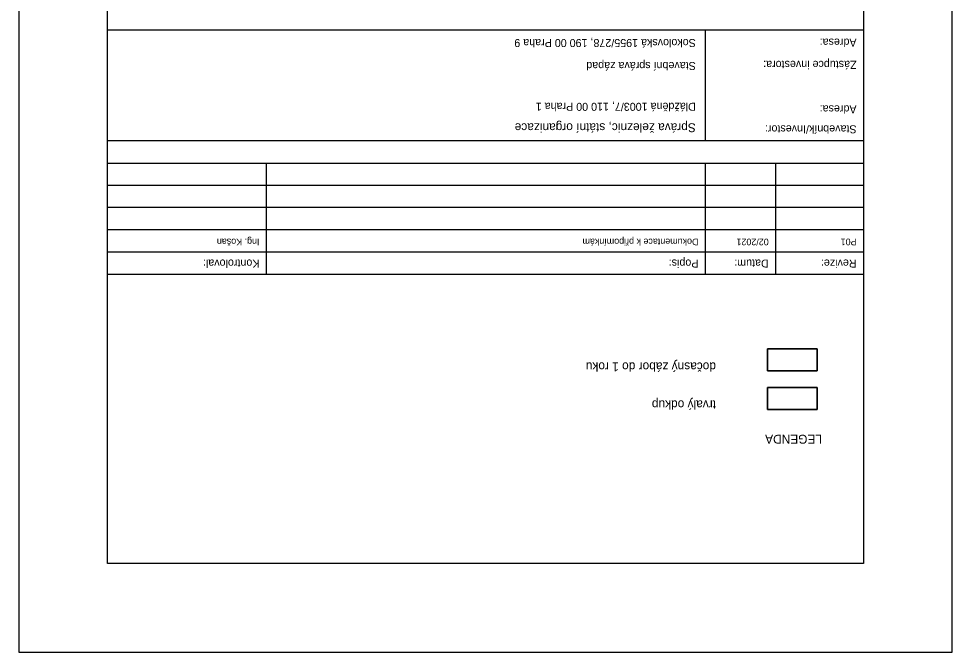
# Model space of a CAD drawing. Extents: x -728452 to -728347, y -1073107 to -1072959.
# Drawn here: x -728452.3 to -728347.3, y -1073107.3 to -1073036.1 of the extents above; entities that cross this region are included whole.
import ezdxf

# ---------------------------------------------------------------- set-up
doc = ezdxf.new("R2010")
doc.units = 0
for name, color, linetype in [('Default', 7, 'Continuous'), ('Dočasný_do_1_roku_maska', 7, 'Continuous'), ('Dočasný_nad_1_rok_PUPFL', 7, 'Continuous'), ('Ořez', 7, 'Continuous'), ('Rozpiska neměnná', 7, 'Continuous'), ('Trvalý_pro_SŽDC_dle_UMVZST', 7, 'Continuous'), ('Trvalý_XXX_PUPFL', 7, 'Continuous'), ('Věcné_Břemeno_PS_SO', 7, 'Continuous')]:
    doc.layers.add(name, color=color, linetype=linetype)

msp = doc.modelspace()

# ---------------------------------------------------------------- linework, layer by layer
at = {"layer": 'Default'}
msp.add_lwpolyline([(-728347.31, -1072958.8), (-728452.31, -1072958.8), (-728452.31, -1073107.3), (-728347.31, -1073107.3)], close=True, dxfattribs=at)
at = {"layer": 'Dočasný_do_1_roku_maska'}
msp.add_line((-728375.09, -1073037.3), (-728375.09, -1073049.8), dxfattribs=at)
msp.add_lwpolyline([(-728357.31, -1073049.8), (-728442.31, -1073049.8), (-728442.31, -1073037.3), (-728357.31, -1073037.3)], close=True, dxfattribs=at)
at = {"layer": 'Ořez'}
msp.add_lwpolyline([(-728357.31, -1073097.3), (-728442.31, -1073097.3), (-728442.31, -1072967.3), (-728357.31, -1072967.3)], close=True, dxfattribs=at)
at = {"layer": 'Rozpiska neměnná'}
for p, q in [((-728424.46, -1073052.3), (-728424.46, -1073064.8)), ((-728375.09, -1073052.3), (-728375.09, -1073064.8)), ((-728367.19, -1073052.3), (-728367.19, -1073064.8)), ((-728357.31, -1073054.8), (-728442.31, -1073054.8)), ((-728357.31, -1073057.3), (-728442.31, -1073057.3)), ((-728357.31, -1073059.8), (-728442.31, -1073059.8)), ((-728357.31, -1073062.3), (-728442.31, -1073062.3))]:
    msp.add_line(p, q, dxfattribs=at)
msp.add_lwpolyline([(-728357.31, -1073064.8), (-728442.31, -1073064.8), (-728442.31, -1073052.3), (-728357.31, -1073052.3)], close=True, dxfattribs=at)
at = {"layer": 'Trvalý_pro_SŽDC_dle_UMVZST'}
for points in [[(-728362.51, -1073075.65), (-728368.08, -1073075.65), (-728368.08, -1073073.17), (-728362.51, -1073073.17)], [(-728362.51, -1073079.99), (-728368.08, -1073079.99), (-728368.08, -1073077.51), (-728362.51, -1073077.51)], [(-728362.51, -1073079.99), (-728368.08, -1073079.99), (-728368.08, -1073077.51), (-728362.51, -1073077.51)]]:
    msp.add_lwpolyline(points, close=True, dxfattribs=at)
at = {"layer": 'Trvalý_XXX_PUPFL'}
msp.add_lwpolyline([(-728362.51, -1073077.51), (-728368.08, -1073077.51), (-728368.08, -1073079.99), (-728362.51, -1073079.99)], close=True, dxfattribs=at)
at = {"layer": 'Věcné_Břemeno_PS_SO'}
msp.add_lwpolyline([(-728368.08, -1073073.17), (-728368.08, -1073075.65), (-728362.51, -1073075.65), (-728362.51, -1073073.17)], close=True, dxfattribs=at)

# ---------------------------------------------------------------- texts
at = {"layer": 'Dočasný_do_1_roku_maska'}
for s, height, p in [('Adresa:', 0.9, (-728358.08, -1073038.29)), ('Zástupce investora:', 0.9, (-728358.08, -1073040.79)), ('Adresa:', 0.9, (-728358.08, -1073045.79)), ('Správa železnic, státní organizace', 1, (-728376.16, -1073047.81)), ('Stavebník/Investor:', 0.9, (-728358.08, -1073048.04))]:
    msp.add_text(s, height=height, rotation=180, dxfattribs=at).set_placement(p)
at = {"layer": 'Dočasný_nad_1_rok_PUPFL'}
for s, p in [('Sokolovská 1955/278, 190 00 Praha 9', (-728376.16, -1073038.34)), ('Stavební správa západ', (-728376.16, -1073040.92)), ('Dlážděná 1003/7, 110 00 Praha 1', (-728376.16, -1073045.51))]:
    msp.add_text(s, height=0.9, rotation=180, dxfattribs=at).set_placement(p)
at = {"layer": 'Rozpiska neměnná'}
for s, height, p in [('Ing. Košan', 0.75, (-728425.23, -1073060.78)), ('Dokumentace k připomínkám', 0.75, (-728375.86, -1073060.78)), ('02/2021', 0.75, (-728367.96, -1073060.78)), ('P01', 0.75, (-728358.08, -1073060.78)), ('Kontroloval:', 0.9, (-728425.23, -1073063.13)), ('Popis:', 0.9, (-728375.86, -1073063.13)), ('Datum:', 0.9, (-728367.96, -1073063.13)), ('Revize:', 0.9, (-728358.08, -1073063.13))]:
    msp.add_text(s, height=height, rotation=180, dxfattribs=at).set_placement(p)
at = {"layer": 'Trvalý_pro_SŽDC_dle_UMVZST'}
for s, p in [('dočasný zábor do 1 roku', (-728373.89, -1073074.7)), ('trvalý odkup', (-728373.89, -1073078.97)), ('LEGENDA', (-728361.97, -1073082.84))]:
    msp.add_text(s, height=1, rotation=180, dxfattribs=at).set_placement(p)

doc.saveas('drawing.dxf')
